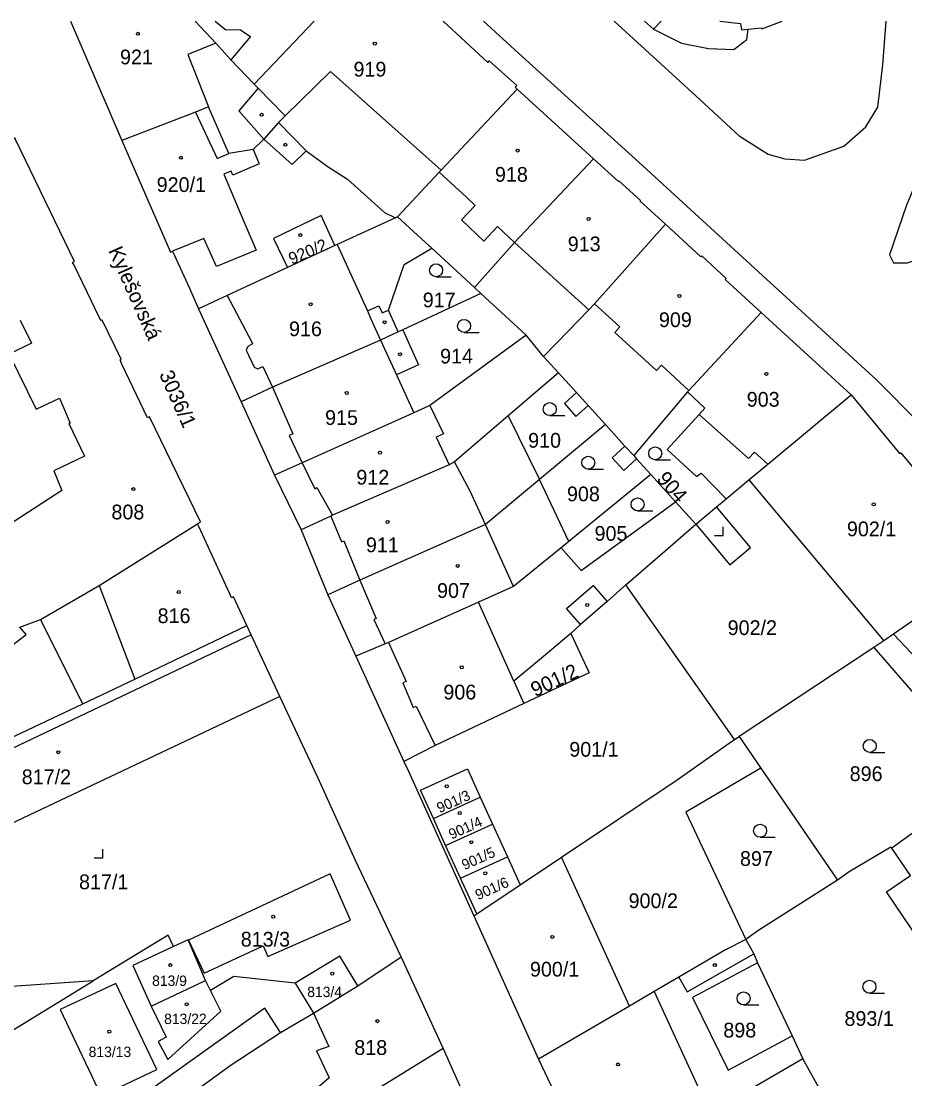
# Model space of a CAD drawing. Extents: x -496682 to -495776, y -1088797 to -1088018.
# Drawn here: x -496295.8 to -496193.9, y -1088141.5 to -1088019.5 of the extents above; entities that cross this region are included whole.
import ezdxf

# ---------------------------------------------------------------- set-up
doc = ezdxf.new("R2010")
doc.units = 0
for name, color, linetype in [('Hranice parcel', 7, 'Continuous'), ('Parcelní čísla', 7, 'Continuous'), ('Pop  PČ popisy', 7, 'Continuous'), ('Vnitřní kresba', 7, 'Continuous'), ('Značky budov', 7, 'Continuous'), ('Značky kultur', 7, 'Continuous')]:
    doc.layers.add(name, color=color, linetype=linetype)

msp = doc.modelspace()

# ---------------------------------------------------------------- linework, layer by layer
at = {"layer": 'Hranice parcel'}
for p, q in [((-496290.12, -1088019.49), (-496284.21, -1088033.27)), ((-496268.93, -1088026.74), (-496262.02, -1088019.49)), ((-496252.41, -1088042.06), (-496252.65, -1088042.17)), ((-496259.65, -1088045.38), (-496265.09, -1088047.92)), ((-496243.53, -1088050.21), (-496248.45, -1088045.69)), ((-496242.78, -1088050.9), (-496251.78, -1088055.1)), ((-496243.53, -1088050.21), (-496242.78, -1088050.9)), ((-496242.78, -1088050.9), (-496237.54, -1088055.74)), ((-496275.35, -1088052.7), (-496270.45, -1088063.42)), ((-496200.06, -1088062.62), (-496210.45, -1088053.11)), ((-496251.78, -1088055.1), (-496252.31, -1088055.35)), ((-496235.54, -1088058.2), (-496237.54, -1088055.74)), ((-496235.54, -1088058.2), (-496233.84, -1088060.08)), ((-496270.45, -1088063.42), (-496266.61, -1088071.89)), ((-496239.62, -1088065.03), (-496236.01, -1088072.37)), ((-496228.41, -1088066.04), (-496236.01, -1088072.37)), ((-496266.61, -1088071.89), (-496263.53, -1088078.19)), ((-496232.65, -1088079.55), (-496236.01, -1088072.37)), ((-496223.18, -1088071.81), (-496232.65, -1088079.55)), ((-496223.18, -1088071.81), (-496220.32, -1088074.97)), ((-496214.47, -1088074.6), (-496211.87, -1088072.4)), ((-496211.87, -1088072.4), (-496196.3, -1088091)), ((-496220.32, -1088074.97), (-496217.99, -1088077.55)), ((-496263.53, -1088078.19), (-496260.43, -1088085.68)), ((-496232.65, -1088079.55), (-496233.51, -1088080.25)), ((-496213.51, -1088102.38), (-496226.04, -1088084.55)), ((-496260.43, -1088085.68), (-496257.2, -1088092.78)), ((-496288.72, -1088098.27), (-496293.61, -1088088.52)), ((-496269.29, -1088090.31), (-496269.79, -1088089.23)), ((-496269.29, -1088090.31), (-496316.2, -1088112.62)), ((-496265.99, -1088097.42), (-496269.29, -1088090.31)), ((-496196.3, -1088091), (-496197.46, -1088091.77)), ((-496197.46, -1088091.77), (-496212.99, -1088102.02)), ((-496197.46, -1088091.77), (-496183.44, -1088107.88)), ((-496257.2, -1088092.78), (-496251.66, -1088104.94)), ((-496321.41, -1088113.75), (-496288.72, -1088098.27)), ((-496265.99, -1088097.42), (-496312.31, -1088119.35)), ((-496213.51, -1088102.38), (-496212.99, -1088102.02)), ((-496212.99, -1088102.02), (-496210.49, -1088105.69)), ((-496210.49, -1088105.69), (-496201.65, -1088118.63)), ((-496248.26, -1088111.5), (-496242.85, -1088109.04)), ((-496242.85, -1088109.04), (-496241.44, -1088112.14)), ((-496246.86, -1088114.6), (-496248.26, -1088111.5)), ((-496246.86, -1088114.6), (-496241.44, -1088112.14)), ((-496241.44, -1088112.14), (-496239.72, -1088115.94)), ((-496245.14, -1088118.39), (-496246.86, -1088114.6)), ((-496245.14, -1088118.39), (-496239.72, -1088115.94)), ((-496239.72, -1088115.94), (-496238.26, -1088119.15)), ((-496238.26, -1088119.15), (-496233.49, -1088115.96)), ((-496225.65, -1088133.15), (-496233.49, -1088115.96)), ((-496243.27, -1088122.51), (-496245.14, -1088118.39)), ((-496243.27, -1088122.51), (-496238.26, -1088119.15)), ((-496243.59, -1088122.72), (-496243.27, -1088122.51)), ((-496243.59, -1088122.72), (-496236.14, -1088139.28)), ((-496257, -1088130.8), (-496251.99, -1088127.48)), ((-496247.14, -1088138.02), (-496251.99, -1088127.48)), ((-496210.87, -1088128.14), (-496206.88, -1088136.59)), ((-496287.5, -1088130.23), (-496328.55, -1088133.03)), ((-496299.6, -1088137.62), (-496287.5, -1088130.23)), ((-496280.81, -1088133.14), (-496274.56, -1088130.21)), ((-496273.98, -1088131.36), (-496274.56, -1088130.21)), ((-496264.2, -1088130.52), (-496262.1, -1088133.95)), ((-496262.1, -1088133.95), (-496257, -1088130.8)), ((-496225.65, -1088133.15), (-496236.14, -1088139.28)), ((-496265.89, -1088136.18), (-496262.1, -1088133.95)), ((-496206.88, -1088136.59), (-496205.62, -1088139.25)), ((-496241.8, -1088149.94), (-496247.14, -1088138.02)), ((-496205.62, -1088139.25), (-496229.59, -1088153.09)), ((-496203.46, -1088143.17), (-496205.62, -1088139.25))]:
    msp.add_line(p, q, dxfattribs=at)
for points in [[(-496275.76, -1088019.49), (-496273.38, -1088022.04), (-496271.62, -1088023.96), (-496268.93, -1088026.74)], [(-496247.13, -1088019.49), (-496241.99, -1088024.25), (-496241.82, -1088024.06), (-496238.65, -1088026.91), (-496238.84, -1088027.12), (-496238.61, -1088027.35)], [(-496121.59, -1088147.94), (-496135.68, -1088131.58), (-496139.54, -1088127.1), (-496152.9, -1088111.52), (-496154.28, -1088109.93), (-496192.25, -1088065.81), (-496197.08, -1088060.92), (-496210.28, -1088048.82), (-496224.09, -1088036.2), (-496238.46, -1088023.17), (-496242.49, -1088019.49)], [(-496227.42, -1088019.49), (-496218.44, -1088027.69), (-496212.99, -1088032.72), (-496209.64, -1088034.85), (-496207.72, -1088035.39), (-496205.46, -1088035.51), (-496200.9, -1088033.92), (-496198.35, -1088031.67), (-496197, -1088029.41), (-496196.42, -1088024.53), (-496196.02, -1088019.49)], [(-496223.91, -1088019.49), (-496222.87, -1088020.43), (-496219.64, -1088022.03), (-496216.53, -1088022.64), (-496213.6, -1088022.74), (-496212.09, -1088021.59), (-496211.93, -1088020.4), (-496210.42, -1088020.24), (-496210.37, -1088020.38), (-496208.02, -1088019.49)], [(-496189.72, -1088029.38), (-496191.51, -1088035.6), (-496193.69, -1088040.71), (-496195.65, -1088046.45), (-496195.19, -1088047.37), (-496193.56, -1088047.37), (-496191.5, -1088046.66), (-496188.77, -1088044.74), (-496186.3, -1088040.83), (-496185.78, -1088035.84), (-496186.46, -1088026.73), (-496186.84, -1088025.75), (-496187.65, -1088025.2), (-496188.59, -1088025.53), (-496189.26, -1088026.45), (-496189.72, -1088029.38)], [(-496268.93, -1088026.74), (-496268.47, -1088027.22), (-496265.37, -1088030.41), (-496266.13, -1088031.18)], [(-496238.61, -1088027.35), (-496247.36, -1088036.67), (-496247.58, -1088036.9), (-496252.41, -1088042.06)], [(-496229.79, -1088035.36), (-496233.37, -1088032.11), (-496238.61, -1088027.35)], [(-496275.49, -1088077.48), (-496275.13, -1088077.26), (-496281.01, -1088065.15), (-496281.24, -1088065.26), (-496284.2, -1088059.06), (-496284.42, -1088058.56), (-496284.28, -1088058.49), (-496286.47, -1088053.98), (-496286.61, -1088054.04), (-496286.78, -1088053.72), (-496289.73, -1088047.63), (-496289.89, -1088047.33), (-496289.67, -1088047.22), (-496296.43, -1088033.23), (-496296.51, -1088033), (-496296.71, -1088033.1), (-496298.65, -1088029.08)], [(-496269.07, -1088034.31), (-496271.86, -1088034.77), (-496274.23, -1088029.37), (-496275.7, -1088030), (-496284.21, -1088033.27)], [(-496266.13, -1088031.18), (-496267.84, -1088033.11), (-496269.07, -1088034.31)], [(-496266.13, -1088031.18), (-496262.94, -1088034.46), (-496260.4, -1088036.29)], [(-496284.21, -1088033.27), (-496278.6, -1088046.13), (-496278.35, -1088046.03)], [(-496229.79, -1088035.36), (-496238.89, -1088045.04), (-496243.53, -1088050.21)], [(-496221.5, -1088042.93), (-496224.42, -1088040.26), (-496224.36, -1088040.2), (-496226.85, -1088037.91), (-496226.92, -1088037.98), (-496229.79, -1088035.36)], [(-496260.4, -1088036.29), (-496258.16, -1088037.74), (-496253.92, -1088041.57), (-496252.65, -1088042.17)], [(-496259.65, -1088045.38), (-496261.22, -1088041.9), (-496266.73, -1088044.55), (-496265.09, -1088047.92)], [(-496252.65, -1088042.17), (-496259.37, -1088045.25), (-496259.65, -1088045.38)], [(-496248.45, -1088045.69), (-496249.17, -1088045.03), (-496252.41, -1088042.06)], [(-496221.5, -1088042.93), (-496229.68, -1088052.09), (-496230.31, -1088052.79), (-496232.64, -1088055.2), (-496235.54, -1088058.2)], [(-496210.45, -1088053.11), (-496214.59, -1088049.3), (-496214.48, -1088049.18), (-496217.29, -1088046.57), (-496217.41, -1088046.7), (-496221.5, -1088042.93)], [(-496278.35, -1088046.03), (-496276.42, -1088050.3), (-496275.35, -1088052.7)], [(-496252.31, -1088055.35), (-496253.46, -1088052.82), (-496251.65, -1088047.57), (-496248.45, -1088045.69)], [(-496265.09, -1088047.92), (-496272.05, -1088051.15), (-496275.35, -1088052.7)], [(-496210.45, -1088053.11), (-496218.79, -1088062.09), (-496218.96, -1088062.26)], [(-496295.93, -1088054), (-496294.63, -1088056.63), (-496297.22, -1088057.91), (-496294.11, -1088064.26), (-496291.39, -1088062.99), (-496290.17, -1088065.87), (-496290.33, -1088065.93), (-496288.52, -1088069.67), (-496292.07, -1088071.39), (-496291.14, -1088073.66), (-496301.28, -1088080.22)], [(-496252.31, -1088055.35), (-496254.35, -1088056.3), (-496266.82, -1088061.74), (-496270.45, -1088063.42)], [(-496251.78, -1088055.1), (-496249.99, -1088059.14), (-496252.53, -1088060.29), (-496250.53, -1088064.7)], [(-496237.54, -1088055.74), (-496248.69, -1088063.85), (-496250.53, -1088064.7)], [(-496233.84, -1088060.08), (-496236.43, -1088062.3), (-496239.62, -1088065.03)], [(-496233.84, -1088060.08), (-496231.77, -1088062.35), (-496230.42, -1088063.83), (-496228.41, -1088066.04)], [(-496218.96, -1088062.26), (-496221.39, -1088065.17), (-496225.14, -1088069.61)], [(-496218.96, -1088062.26), (-496216.93, -1088064.15), (-496217.59, -1088064.87), (-496221.29, -1088068.92), (-496217.9, -1088072.02), (-496217.36, -1088071.64), (-496214.47, -1088074.6)], [(-496211.87, -1088072.4), (-496209.69, -1088070.6), (-496200.06, -1088062.62)], [(-496200.06, -1088062.62), (-496194.43, -1088069.4), (-496194.32, -1088069.3), (-496189.2, -1088075.46), (-496189.32, -1088075.56), (-496183.71, -1088082.3)], [(-496250.53, -1088064.7), (-496263.4, -1088070.45), (-496266.61, -1088071.89)], [(-496239.62, -1088065.03), (-496245.81, -1088070.34), (-496246.43, -1088070.68), (-496259.9, -1088076.48), (-496260.11, -1088076.62), (-496263.53, -1088078.19)], [(-496225.14, -1088069.61), (-496226.16, -1088068.53), (-496228.41, -1088066.04)], [(-496225.14, -1088069.61), (-496224.82, -1088070.01), (-496223.18, -1088071.81)], [(-496236.01, -1088072.37), (-496242.26, -1088077.59), (-496256.74, -1088083.98), (-496260.43, -1088085.68)], [(-496233.51, -1088080.25), (-496231.22, -1088082.89), (-496220.32, -1088074.97)], [(-496217.99, -1088077.55), (-496215.59, -1088075.54), (-496214.47, -1088074.6)], [(-496293.61, -1088088.52), (-496286.81, -1088084.63), (-496275.49, -1088077.48)], [(-496269.79, -1088089.23), (-496271.33, -1088085.91), (-496271.56, -1088086.03), (-496271.79, -1088085.51), (-496275.33, -1088077.82), (-496275.49, -1088077.48)], [(-496226.04, -1088084.55), (-496222.11, -1088081.13), (-496217.99, -1088077.55)], [(-496233.51, -1088080.25), (-496239.01, -1088084.74), (-496243.07, -1088086.55), (-496253.46, -1088091.18), (-496253.83, -1088091.34), (-496257.2, -1088092.78)], [(-496183.71, -1088082.3), (-496195.19, -1088090.23), (-496196.3, -1088091)], [(-496226.04, -1088084.55), (-496228.23, -1088086.45), (-496231.29, -1088089.11), (-496232.41, -1088090.16)], [(-496318.3, -1088110.48), (-496307.01, -1088099.28), (-496295.23, -1088090.25), (-496295.99, -1088089.43), (-496293.61, -1088088.52)], [(-496288.72, -1088098.27), (-496282.72, -1088095.43), (-496269.79, -1088089.23)], [(-496232.41, -1088090.16), (-496235.56, -1088092.82), (-496239, -1088095.64), (-496237.83, -1088098.24)], [(-496232.41, -1088090.16), (-496230.3, -1088094.69), (-496237.83, -1088098.24)], [(-496251.99, -1088127.48), (-496257.26, -1088116.34), (-496261.61, -1088106.78), (-496265.99, -1088097.42)], [(-496237.83, -1088098.24), (-496248.04, -1088103.06), (-496251.66, -1088104.94)], [(-496233.49, -1088115.96), (-496220.27, -1088107.11), (-496214.12, -1088102.81), (-496213.51, -1088102.38)], [(-496251.66, -1088104.94), (-496251.19, -1088105.96), (-496243.59, -1088122.72)], [(-496248.26, -1088111.5), (-496249.75, -1088108.22), (-496244.33, -1088105.76), (-496242.85, -1088109.04)], [(-496210.49, -1088105.69), (-496219.13, -1088110.78), (-496212.23, -1088125.45)], [(-496183.44, -1088107.88), (-496189.41, -1088111.49), (-496189.82, -1088110.92), (-496195.38, -1088114.92)], [(-496195.38, -1088114.92), (-496195.47, -1088114.8), (-496200.29, -1088117.66), (-496201.65, -1088118.63)], [(-496191.24, -1088126.97), (-496196, -1088119.97), (-496193.23, -1088118.07), (-496195.38, -1088114.92)], [(-496257.82, -1088123.22), (-496260.16, -1088117.88), (-496276.5, -1088125.53), (-496274.71, -1088129.36), (-496267.9, -1088126.18), (-496267.36, -1088127.41), (-496257.82, -1088123.22)], [(-496201.65, -1088118.63), (-496210.81, -1088124.46), (-496212.23, -1088125.45)], [(-496278.24, -1088126.28), (-496278.87, -1088124.96), (-496287.5, -1088130.23)], [(-496278.24, -1088126.28), (-496282.93, -1088128.45), (-496280.81, -1088133.14)], [(-496274.56, -1088130.21), (-496276.55, -1088125.49), (-496278.24, -1088126.28)], [(-496212.23, -1088125.45), (-496214.56, -1088126.66), (-496219.96, -1088129.82), (-496222.8, -1088131.48), (-496225.65, -1088133.15)], [(-496212.23, -1088125.45), (-496211.28, -1088127.13), (-496210.87, -1088128.14)], [(-496257, -1088130.8), (-496259.07, -1088127.4), (-496264.2, -1088130.52)], [(-496210.87, -1088128.14), (-496218.36, -1088132.15), (-496214.27, -1088140.54), (-496206.88, -1088136.59)], [(-496264.2, -1088130.52), (-496271.27, -1088129.74), (-496273.98, -1088131.36)], [(-496284.92, -1088130.53), (-496291.31, -1088133.56), (-496286.59, -1088143.52), (-496280.17, -1088140.48), (-496284.92, -1088130.53)], [(-496280.81, -1088133.14), (-496279.08, -1088136.73), (-496280.02, -1088137.23), (-496278.91, -1088139.32), (-496272.78, -1088133.72), (-496273.98, -1088131.36)], [(-496265.89, -1088136.18), (-496267.72, -1088133.38), (-496298.45, -1088155.33)], [(-496262.1, -1088133.95), (-496260.32, -1088137.8), (-496261.74, -1088138.32), (-496260.3, -1088141.44), (-496262.22, -1088143.07), (-496260.45, -1088146.79)], [(-496295.42, -1088158.88), (-496286.46, -1088150.74), (-496280.26, -1088146.23), (-496271.7, -1088140.01), (-496265.89, -1088136.18)], [(-496260.45, -1088146.79), (-496257.27, -1088144.28), (-496247.14, -1088138.02)], [(-496236.14, -1088139.28), (-496230.41, -1088151.36), (-496229.59, -1088153.09)]]:
    msp.add_lwpolyline(points, dxfattribs=at)
at = {"layer": 'Vnitřní kresba'}
for p, q in [((-496273.46, -1088019.49), (-496272.22, -1088020.47)), ((-496222.87, -1088020.43), (-496221.98, -1088019.49)), ((-496215.23, -1088019.49), (-496212.81, -1088019.74)), ((-496212.81, -1088019.74), (-496212.7, -1088020.48)), ((-496272.22, -1088020.47), (-496270.61, -1088020.44)), ((-496269.37, -1088021.26), (-496271.62, -1088023.96)), ((-496270.61, -1088020.44), (-496269.37, -1088021.26)), ((-496212.7, -1088020.48), (-496211.93, -1088020.4)), ((-496273.38, -1088022.04), (-496276.59, -1088023.33)), ((-496276.59, -1088023.33), (-496274.23, -1088029.37)), ((-496265.37, -1088030.41), (-496260.12, -1088025.28)), ((-496260.12, -1088025.28), (-496247.36, -1088036.67)), ((-496268.47, -1088027.22), (-496270.71, -1088029.82)), ((-496275.7, -1088030), (-496273.23, -1088035.35)), ((-496270.71, -1088029.82), (-496267.84, -1088033.11)), ((-496267.84, -1088033.11), (-496264.55, -1088036.03)), ((-496273.23, -1088035.35), (-496271.86, -1088034.77)), ((-496269.07, -1088034.31), (-496268.35, -1088035.97)), ((-496264.55, -1088036.03), (-496262.94, -1088034.46)), ((-496268.35, -1088035.97), (-496271.4, -1088037.27)), ((-496271.61, -1088036.79), (-496272.46, -1088037.16)), ((-496272.46, -1088037.16), (-496270.12, -1088042.62)), ((-496271.4, -1088037.27), (-496271.61, -1088036.79)), ((-496247.58, -1088036.9), (-496244.46, -1088039.81)), ((-496244.46, -1088039.81), (-496243.43, -1088040.77)), ((-496243.43, -1088040.77), (-496245.01, -1088042.43)), ((-496270.12, -1088042.62), (-496268.72, -1088045.9)), ((-496245.01, -1088042.43), (-496242.44, -1088044.87)), ((-496242.44, -1088044.87), (-496240.85, -1088043.19)), ((-496240.85, -1088043.19), (-496238.89, -1088045.04)), ((-496274.74, -1088044.56), (-496278.35, -1088046.03)), ((-496273.29, -1088047.81), (-496274.74, -1088044.56)), ((-496268.72, -1088045.9), (-496273.29, -1088047.81)), ((-496259.37, -1088045.25), (-496255.88, -1088052.93)), ((-496238.89, -1088045.04), (-496230.31, -1088052.79)), ((-496272.05, -1088051.15), (-496269.23, -1088056.55)), ((-496229.68, -1088052.09), (-496226.75, -1088054.78)), ((-496255.88, -1088052.93), (-496254.55, -1088052.32)), ((-496255.88, -1088052.93), (-496255.51, -1088053.75)), ((-496254.55, -1088052.32), (-496254.18, -1088053.14)), ((-496254.18, -1088053.14), (-496253.46, -1088052.82)), ((-496255.51, -1088053.75), (-496254.35, -1088056.3)), ((-496226.75, -1088054.78), (-496227.32, -1088055.43)), ((-496227.32, -1088055.43), (-496222.53, -1088059.8)), ((-496269.13, -1088056.74), (-496269.69, -1088057.04)), ((-496269.23, -1088056.55), (-496269.13, -1088056.74)), ((-496254.35, -1088056.3), (-496252.53, -1088060.29)), ((-496269.69, -1088057.04), (-496269.85, -1088057.45)), ((-496269.85, -1088057.45), (-496268.94, -1088059.43)), ((-496268.94, -1088059.43), (-496268.5, -1088059.6)), ((-496268.5, -1088059.6), (-496267.96, -1088059.33)), ((-496267.96, -1088059.33), (-496266.82, -1088061.74)), ((-496222.53, -1088059.8), (-496221.96, -1088059.18)), ((-496221.96, -1088059.18), (-496218.79, -1088062.09)), ((-496266.82, -1088061.74), (-496264.49, -1088067.11)), ((-496231.77, -1088062.35), (-496233.15, -1088063.61)), ((-496248.69, -1088063.85), (-496247.1, -1088067.1)), ((-496233.15, -1088063.61), (-496231.83, -1088065.11)), ((-496231.83, -1088065.11), (-496230.42, -1088063.83)), ((-496217.59, -1088064.87), (-496211.89, -1088069.96)), ((-496264.49, -1088067.11), (-496264.89, -1088067.29)), ((-496264.89, -1088067.29), (-496263.4, -1088070.45)), ((-496247.1, -1088067.1), (-496247.94, -1088067.51)), ((-496247.94, -1088067.51), (-496246.43, -1088070.68)), ((-496226.16, -1088068.53), (-496227.64, -1088069.87)), ((-496211.89, -1088069.96), (-496211.23, -1088069.22)), ((-496211.23, -1088069.22), (-496209.69, -1088070.6)), ((-496244.01, -1088073.72), (-496245.81, -1088070.34)), ((-496227.64, -1088069.87), (-496226.3, -1088071.35)), ((-496226.3, -1088071.35), (-496224.82, -1088070.01)), ((-496263.4, -1088070.45), (-496261.96, -1088073.47)), ((-496261.96, -1088073.47), (-496261.71, -1088073.32)), ((-496261.71, -1088073.32), (-496259.9, -1088076.48)), ((-496242.26, -1088077.59), (-496244.01, -1088073.72)), ((-496211.69, -1088080.24), (-496215.59, -1088075.54)), ((-496260.11, -1088076.62), (-496258.88, -1088079.59)), ((-496239.01, -1088084.74), (-496242.26, -1088077.59)), ((-496217.99, -1088077.55), (-496214.05, -1088082.21)), ((-496258.88, -1088079.59), (-496258.6, -1088079.47)), ((-496258.6, -1088079.47), (-496256.74, -1088083.98)), ((-496214.05, -1088082.21), (-496211.69, -1088080.24)), ((-496286.81, -1088084.63), (-496282.72, -1088095.43)), ((-496256.74, -1088083.98), (-496254.87, -1088088.42)), ((-496232.89, -1088087.27), (-496229.83, -1088084.61)), ((-496229.83, -1088084.61), (-496228.23, -1088086.45)), ((-496239, -1088095.64), (-496243.07, -1088086.55)), ((-496231.29, -1088089.11), (-496232.89, -1088087.27)), ((-496254.87, -1088088.42), (-496255.14, -1088088.54)), ((-496255.14, -1088088.54), (-496253.83, -1088091.34)), ((-496253.46, -1088091.18), (-496251.4, -1088095.68)), ((-496189.91, -1088095.8), (-496195.19, -1088090.23)), ((-496251.4, -1088095.68), (-496251.77, -1088095.85)), ((-496251.77, -1088095.85), (-496250.61, -1088098.7)), ((-496250.61, -1088098.7), (-496250.26, -1088098.52)), ((-496250.26, -1088098.52), (-496248.04, -1088103.06)), ((-496218.97, -1088131.5), (-496211.28, -1088127.13)), ((-496219.96, -1088129.82), (-496218.97, -1088131.5)), ((-496222.8, -1088131.48), (-496217.11, -1088143.84))]:
    msp.add_line(p, q, dxfattribs=at)
at = {"layer": 'Značky budov'}
for centre in [(-496282.36, -1088020.94), (-496255.02, -1088022.08), (-496268.08, -1088030.29), (-496265.33, -1088033.75), (-496238.55, -1088034.42), (-496277.4, -1088035.25), (-496230.36, -1088042.31), (-496263.6, -1088044.18), (-496262.42, -1088052.15), (-496219.87, -1088051.2), (-496253.9, -1088054.23), (-496252.11, -1088057.92), (-496209.84, -1088060.19), (-496258.26, -1088062.39), (-496254.43, -1088069.28), (-496282.87, -1088073.49), (-496197.46, -1088075.25), (-496253.55, -1088077.28), (-496245.45, -1088082.35), (-496277.64, -1088085.37), (-496230.51, -1088086.86), (-496244.99, -1088094.05), (-496291.55, -1088103.85), (-496246.72, -1088107.78), (-496245.22, -1088110.87), (-496243.9, -1088114.24), (-496242.28, -1088117.82), (-496266.74, -1088122.83), (-496234.54, -1088125.16), (-496278.63, -1088128.42), (-496215.79, -1088128.42), (-496259.94, -1088129.4), (-496276.73, -1088132.93), (-496254.72, -1088134.89), (-496285.66, -1088136.1), (-496226.95, -1088139.88)]:
    msp.add_circle(centre, 0.175, dxfattribs=at)
at = {"layer": 'Značky kultur'}
for p, q in [((-496247.95, -1088048.99), (-496246.2, -1088048.99)), ((-496244.73, -1088055.4), (-496242.98, -1088055.4)), ((-496234.84, -1088065.01), (-496233.09, -1088065.01)), ((-496222.67, -1088070.11), (-496220.92, -1088070.11)), ((-496230.39, -1088071.19), (-496228.64, -1088071.19)), ((-496224.7, -1088076), (-496222.95, -1088076)), ((-496215.82, -1088078.84), (-496214.82, -1088078.84)), ((-496214.82, -1088078.84), (-496214.82, -1088077.84)), ((-496197.92, -1088103.88), (-496196.17, -1088103.88)), ((-496210.57, -1088113.67), (-496208.82, -1088113.67)), ((-496286.39, -1088116.05), (-496286.39, -1088115.05)), ((-496287.39, -1088116.05), (-496286.39, -1088116.05)), ((-496197.95, -1088131.66), (-496196.2, -1088131.66)), ((-496212.48, -1088133.01), (-496210.73, -1088133.01))]:
    msp.add_line(p, q, dxfattribs=at)
for centre in [(-496247.95, -1088048.24), (-496244.73, -1088054.65), (-496234.84, -1088064.26), (-496222.67, -1088069.36), (-496230.39, -1088070.44), (-496224.7, -1088075.25), (-496197.92, -1088103.13), (-496210.57, -1088112.92), (-496197.95, -1088130.91), (-496212.48, -1088132.26)]:
    msp.add_circle(centre, 0.75, dxfattribs=at)

# ---------------------------------------------------------------- texts
at = {"layer": 'Parcelní čísla'}
for s, height, p in [('921', 1.7, (-496284.42, -1088024.47)), ('919', 1.7, (-496257.48, -1088025.88)), ('920/1', 1.7, (-496280.19, -1088039.2)), ('918', 1.7, (-496241.16, -1088038.02)), ('913', 1.7, (-496232.76, -1088046.04)), ('917', 1.7, (-496249.49, -1088052.51)), ('909', 1.7, (-496222.24, -1088054.79)), ('916', 1.7, (-496264.92, -1088055.84)), ('914', 1.7, (-496247.49, -1088058.99)), ('903', 1.7, (-496212.11, -1088063.98)), ('915', 1.7, (-496260.76, -1088066.08)), ('910', 1.7, (-496237.33, -1088068.71)), ('912', 1.7, (-496257.15, -1088072.97)), ('908', 1.7, (-496232.85, -1088074.89)), ('808', 1.7, (-496285.41, -1088076.98)), ('905', 1.7, (-496229.67, -1088079.45)), ('902/1', 1.7, (-496200.55, -1088078.93)), ('911', 1.7, (-496256.05, -1088080.77)), ('907', 1.7, (-496247.84, -1088086.04)), ('816', 1.7, (-496280.08, -1088088.95)), ('902/2', 1.7, (-496214.31, -1088090.33)), ('906', 1.7, (-496247.11, -1088097.76)), ('901/1', 1.7, (-496232.58, -1088104.37)), ('817/2', 1.7, (-496295.76, -1088107.54)), ('896', 1.7, (-496200.23, -1088107.18)), ('897', 1.7, (-496212.89, -1088116.97)), ('817/1', 1.7, (-496289.15, -1088119.66)), ('900/2', 1.7, (-496225.74, -1088121.84)), ('813/3', 1.7, (-496270.49, -1088126.28)), ('900/1', 1.7, (-496237.12, -1088129.74)), ('813/9', 1.2, (-496280.72, -1088130.82)), ('813/4', 1.2, (-496262.82, -1088132.11)), ('893/1', 1.7, (-496200.83, -1088135.43)), ('813/22', 1.2, (-496279.33, -1088135.22)), ('898', 1.7, (-496214.81, -1088136.77)), ('818', 1.7, (-496257.39, -1088138.78)), ('813/13', 1.2, (-496288.04, -1088139.03))]:
    msp.add_text(s, height=height, dxfattribs=at).set_placement(p)
for s, height, rotation, p in [('920/2', 1.378, 23, (-496264.61, -1088047.61)), ('3036/1', 1.7, 294, (-496279.93, -1088060.24)), ('904', 1.7, 311, (-496222.59, -1088072.36)), ('901/2', 1.7, 25, (-496236.53, -1088097.51)), ('901/3', 1.2, 24, (-496247.55, -1088110.9)), ('901/4', 1.2, 24, (-496246.17, -1088113.94)), ('901/5', 1.2, 24, (-496244.67, -1088117.47)), ('901/6', 1.2, 24, (-496243.11, -1088120.94))]:
    msp.add_text(s, height=height, rotation=rotation, dxfattribs=at).set_placement(p)
at = {"layer": 'Pop  PČ popisy'}
msp.add_text('Kylešovská', height=1.7, rotation=294, dxfattribs=at).set_placement((-496285.8, -1088045.95))

doc.saveas('drawing.dxf')
